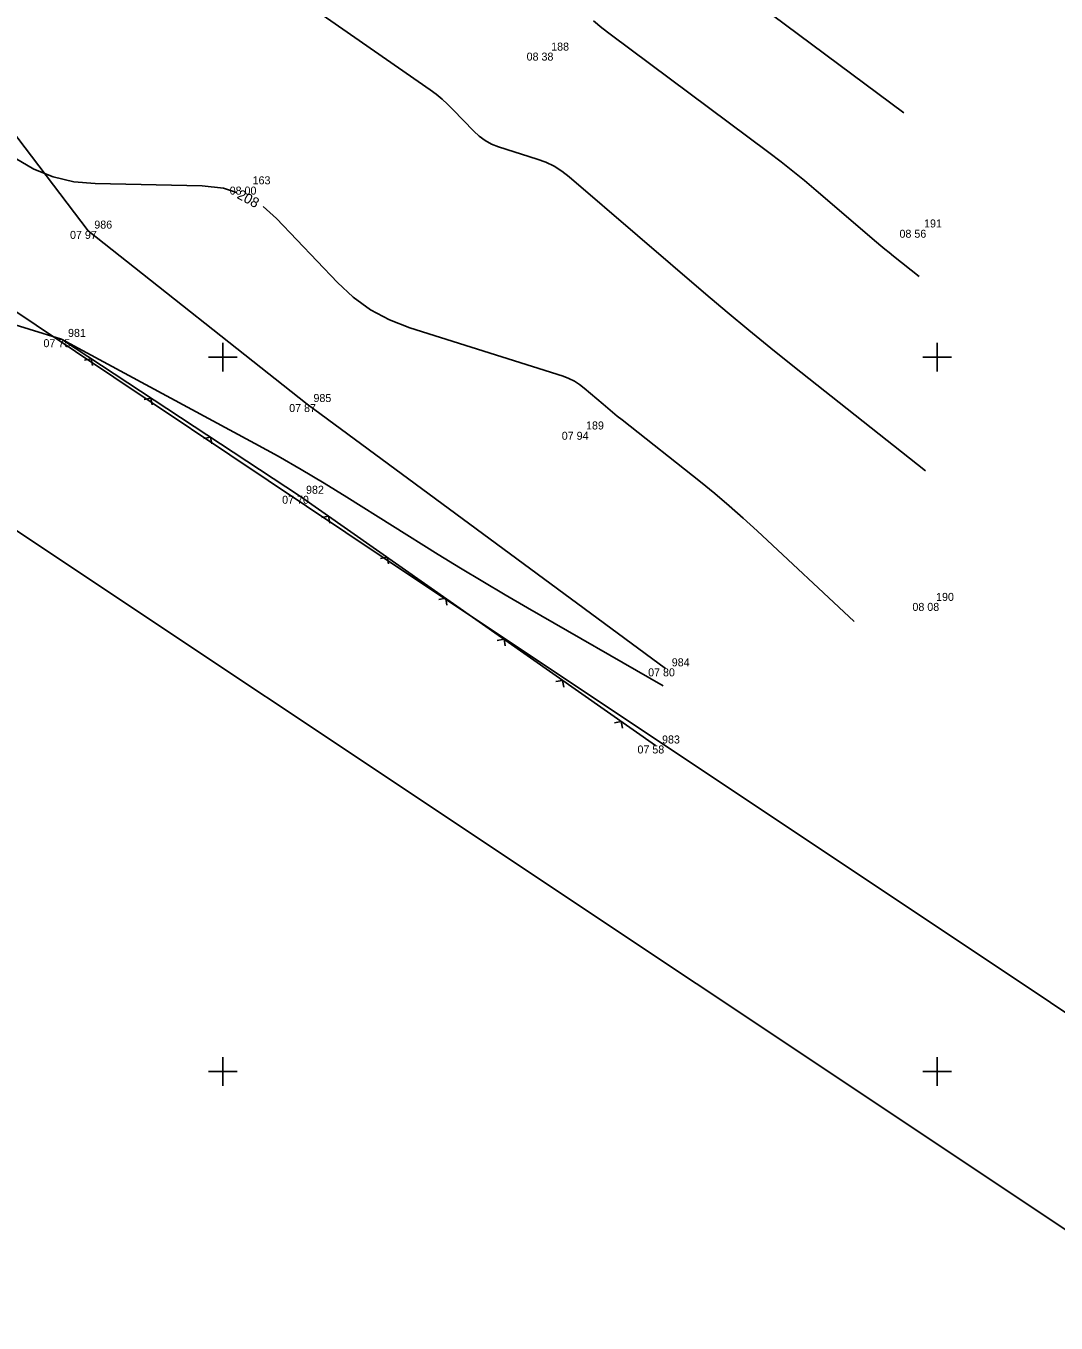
# Model space of a CAD drawing. Extents: x -711234 to -710007, y -1026313 to -1025448.
# Drawn here: x -710881.89 to -710845.84, y -1026008.8 to -1025963.41 of the extents above; entities that cross this region are included whole.
import ezdxf

# ---------------------------------------------------------------- set-up
doc = ezdxf.new("R2010")
doc.units = 0
for name, color, linetype in [('Ex_Contour Labels', 7, 'Continuous'), ('Ex_Major Contours', 7, 'Continuous'), ('Ex_Minor Contours', 7, 'Continuous'), ('Z_body', 7, 'Continuous'), ('Z_body_cisla', 7, 'Continuous'), ('Z_body_vysky_redukovane', 7, 'Continuous'), ('Z_hektometricka_sit', 7, 'Continuous'), ('Z_katastr_hranice', 7, 'Continuous'), ('Z_ploty', 7, 'Continuous'), ('Z_ploty_znacky', 7, 'Continuous'), ('Z_pole_rozhranni', 7, 'Continuous')]:
    doc.layers.add(name, color=color, linetype=linetype)

# ---------------------------------------------------------------- blocks, each defined once
blk = doc.blocks.new('POINT_DISPLAY')
blk.add_line((0, 0), (0, 0))
blk = doc.blocks.new('Z212')
for p, q in [((-0.17, 0.17), (0, 0)), ((0, 0), (0.17, 0.17))]:
    blk.add_line(p, q)

msp = doc.modelspace()

# ---------------------------------------------------------------- linework, layer by layer
at = {"layer": 'Ex_Major Contours'}
for points in [[(-710874.518, -1025969.232), (-710874.981, -1025969.083), (-710875.722, -1025968.999), (-710879.472, -1025968.925), (-710880.219, -1025968.859), (-710880.935, -1025968.689), (-710881.617, -1025968.415), (-710882.267, -1025968.039)], [(-710852.903, -1025984.254), (-710856.304, -1025981.072), (-710856.786, -1025980.63), (-710857.278, -1025980.198), (-710857.778, -1025979.776), (-710858.287, -1025979.364), (-710861.027, -1025977.194), (-710861.196, -1025977.059), (-710861.363, -1025976.923), (-710861.529, -1025976.784), (-710861.694, -1025976.644), (-710862.35, -1025976.082), (-710862.519, -1025975.951), (-710862.699, -1025975.838), (-710862.889, -1025975.745), (-710863.09, -1025975.67), (-710868.461, -1025973.97), (-710869.171, -1025973.697), (-710869.83, -1025973.341), (-710870.437, -1025972.905), (-710870.994, -1025972.386), (-710873.118, -1025970.149), (-710873.594, -1025969.731)]]:
    msp.add_lwpolyline(points, dxfattribs=at)
at = {"layer": 'Ex_Minor Contours'}
for points in [[(-710850.412, -1025978.975), (-710855.053, -1025975.3), (-710855.823, -1025974.684), (-710856.588, -1025974.06), (-710857.346, -1025973.429), (-710858.097, -1025972.79), (-710862.883, -1025968.684), (-710863.138, -1025968.487), (-710863.408, -1025968.318), (-710863.695, -1025968.177), (-710863.997, -1025968.064), (-710865.355, -1025967.635), (-710865.598, -1025967.541), (-710865.823, -1025967.419), (-710866.031, -1025967.27), (-710866.222, -1025967.093), (-710866.948, -1025966.327), (-710867.134, -1025966.141), (-710867.329, -1025965.965), (-710867.532, -1025965.799), (-710867.745, -1025965.643), (-710873.857, -1025961.383)], [(-710851.17, -1025966.45), (-710856.671, -1025962.346)], [(-710850.636, -1025972.173), (-710851.534, -1025971.461), (-710851.684, -1025971.342), (-710851.831, -1025971.221), (-710851.978, -1025971.099), (-710852.124, -1025970.976), (-710854.238, -1025969.161), (-710854.642, -1025968.821), (-710855.051, -1025968.487), (-710855.466, -1025968.161), (-710855.887, -1025967.842), (-710861.44, -1025963.699), (-710861.737, -1025963.469), (-710862.025, -1025963.229)], [(-710859.59, -1025986.504), (-710864.334, -1025983.778), (-710865.122, -1025983.32), (-710865.906, -1025982.855), (-710866.685, -1025982.382), (-710867.46, -1025981.902), (-710870.659, -1025979.897), (-710871.454, -1025979.408), (-710872.256, -1025978.932), (-710873.066, -1025978.469), (-710873.883, -1025978.02), (-710880.65, -1025974.37)]]:
    msp.add_lwpolyline(points, dxfattribs=at)
at = {"layer": 'Z_hektometricka_sit'}
for p, q in [((-710875, -1025974.5), (-710875, -1025975.5)), ((-710850, -1025974.5), (-710850, -1025975.5)), ((-710875.5, -1025975), (-710874.5, -1025975)), ((-710850.5, -1025975), (-710849.5, -1025975)), ((-710875, -1025999.5), (-710875, -1026000.5)), ((-710850, -1025999.5), (-710850, -1026000.5)), ((-710875.5, -1026000), (-710874.5, -1026000)), ((-710850.5, -1026000), (-710849.5, -1026000))]:
    msp.add_line(p, q, dxfattribs=at)
at = {"layer": 'Z_katastr_hranice'}
for points in [[(-710652.49, -1026122.99), (-710669.64, -1026111.59), (-710687.05, -1026100.69), (-710724.42, -1026078.47), (-710779.86, -1026042.07), (-710822.71, -1026013.14), (-710869.36, -1025982.03), (-710882.89, -1025972.98)], [(-710652.86, -1026130.08), (-710691.92, -1026105.11), (-710727.6, -1026083.56), (-710783.18, -1026047.07), (-710888.56, -1025976.86)]]:
    msp.add_lwpolyline(points, dxfattribs=at)
at = {"layer": 'Z_ploty'}
for p, q in [((-710884.23, -1025973.27), (-710880.65, -1025974.37)), ((-710880.65, -1025974.37), (-710872.32, -1025979.85)), ((-710872.32, -1025979.85), (-710859.86, -1025988.59))]:
    msp.add_line(p, q, dxfattribs=at)
at = {"layer": 'Z_pole_rozhranni'}
for p, q in [((-710879.72, -1025970.58), (-710884.84, -1025963.84)), ((-710872.05, -1025976.64), (-710879.72, -1025970.58)), ((-710859.51, -1025985.89), (-710872.05, -1025976.64))]:
    msp.add_line(p, q, dxfattribs=at)

# ---------------------------------------------------------------- block references
at = {"layer": 'Z_body'}
for p in [(-710863.74, -1025964.34), (-710874.18, -1025969.03), (-710879.72, -1025970.58), (-710850.69, -1025970.54), (-710880.65, -1025974.37), (-710872.05, -1025976.64), (-710862.51, -1025977.61), (-710872.32, -1025979.85), (-710850.26, -1025983.6), (-710859.51, -1025985.89), (-710859.86, -1025988.59)]:
    msp.add_blockref('POINT_DISPLAY', p, dxfattribs=at)
at = {"layer": 'Z_ploty_znacky'}
for p, rotation in [((-710879.61, -1025975.06), 146.7), ((-710879.61, -1025975.06), 146.7), ((-710877.52, -1025976.43), 146.7), ((-710877.52, -1025976.43), 146.7), ((-710875.43, -1025977.8), 146.7), ((-710875.43, -1025977.8), 146.7), ((-710871.3, -1025980.57), 145), ((-710869.25, -1025982), 145), ((-710867.2, -1025983.44), 145), ((-710865.16, -1025984.87), 145), ((-710863.11, -1025986.31), 145), ((-710861.06, -1025987.75), 145)]:
    msp.add_blockref('Z212', p, dxfattribs=dict(at, rotation=rotation))

# ---------------------------------------------------------------- texts
at = {"layer": 'Ex_Contour Labels'}
msp.add_text('208', height=0.35, rotation=331.5953, dxfattribs=at).set_placement((-710874.537, -1025969.42))
at = {"layer": 'Z_body_cisla'}
for s, p in [('188', (-710863.51, -1025964.27)), ('163', (-710873.96, -1025968.95)), ('986', (-710879.5, -1025970.5)), ('191', (-710850.46, -1025970.46)), ('981', (-710880.42, -1025974.29)), ('985', (-710871.83, -1025976.57)), ('189', (-710862.29, -1025977.53)), ('982', (-710872.09, -1025979.78)), ('190', (-710850.04, -1025983.53)), ('984', (-710859.29, -1025985.82)), ('983', (-710859.63, -1025988.52))]:
    msp.add_text(s, height=0.28, dxfattribs=at).set_placement(p)
at = {"layer": 'Z_body_vysky_redukovane'}
for s, p in [('08 38', (-710864.37, -1025964.62)), ('08 00', (-710874.763, -1025969.31)), ('07 97', (-710880.35, -1025970.86)), ('08 56', (-710851.32, -1025970.82)), ('07 75', (-710881.28, -1025974.65)), ('07 87', (-710872.68, -1025976.92)), ('07 94', (-710863.14, -1025977.89)), ('07 70', (-710872.927, -1025980.13)), ('08 08', (-710850.867, -1025983.88)), ('07 80', (-710860.117, -1025986.17)), ('07 58', (-710860.49, -1025988.87))]:
    msp.add_text(s, height=0.28, dxfattribs=at).set_placement(p)

doc.saveas('drawing.dxf')
